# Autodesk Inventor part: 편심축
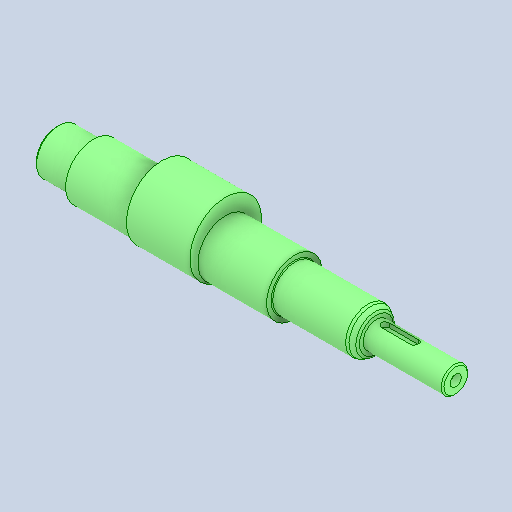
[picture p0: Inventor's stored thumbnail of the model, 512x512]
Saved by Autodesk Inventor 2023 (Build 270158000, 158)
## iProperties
Created: 2024-09
Part Number: 편심축
Material: 강철, 탄소
Document SubType Name: Modeling
Designer: asung
Density: 7.85 g/cm^3
Appearance: 기본값
Author: jhkim
Sending System: Autodesk Inventor 2025
Preprocessor: ST-DEVELOPER v20
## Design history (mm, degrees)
feature "솔리드1"
node "솔리드2"
